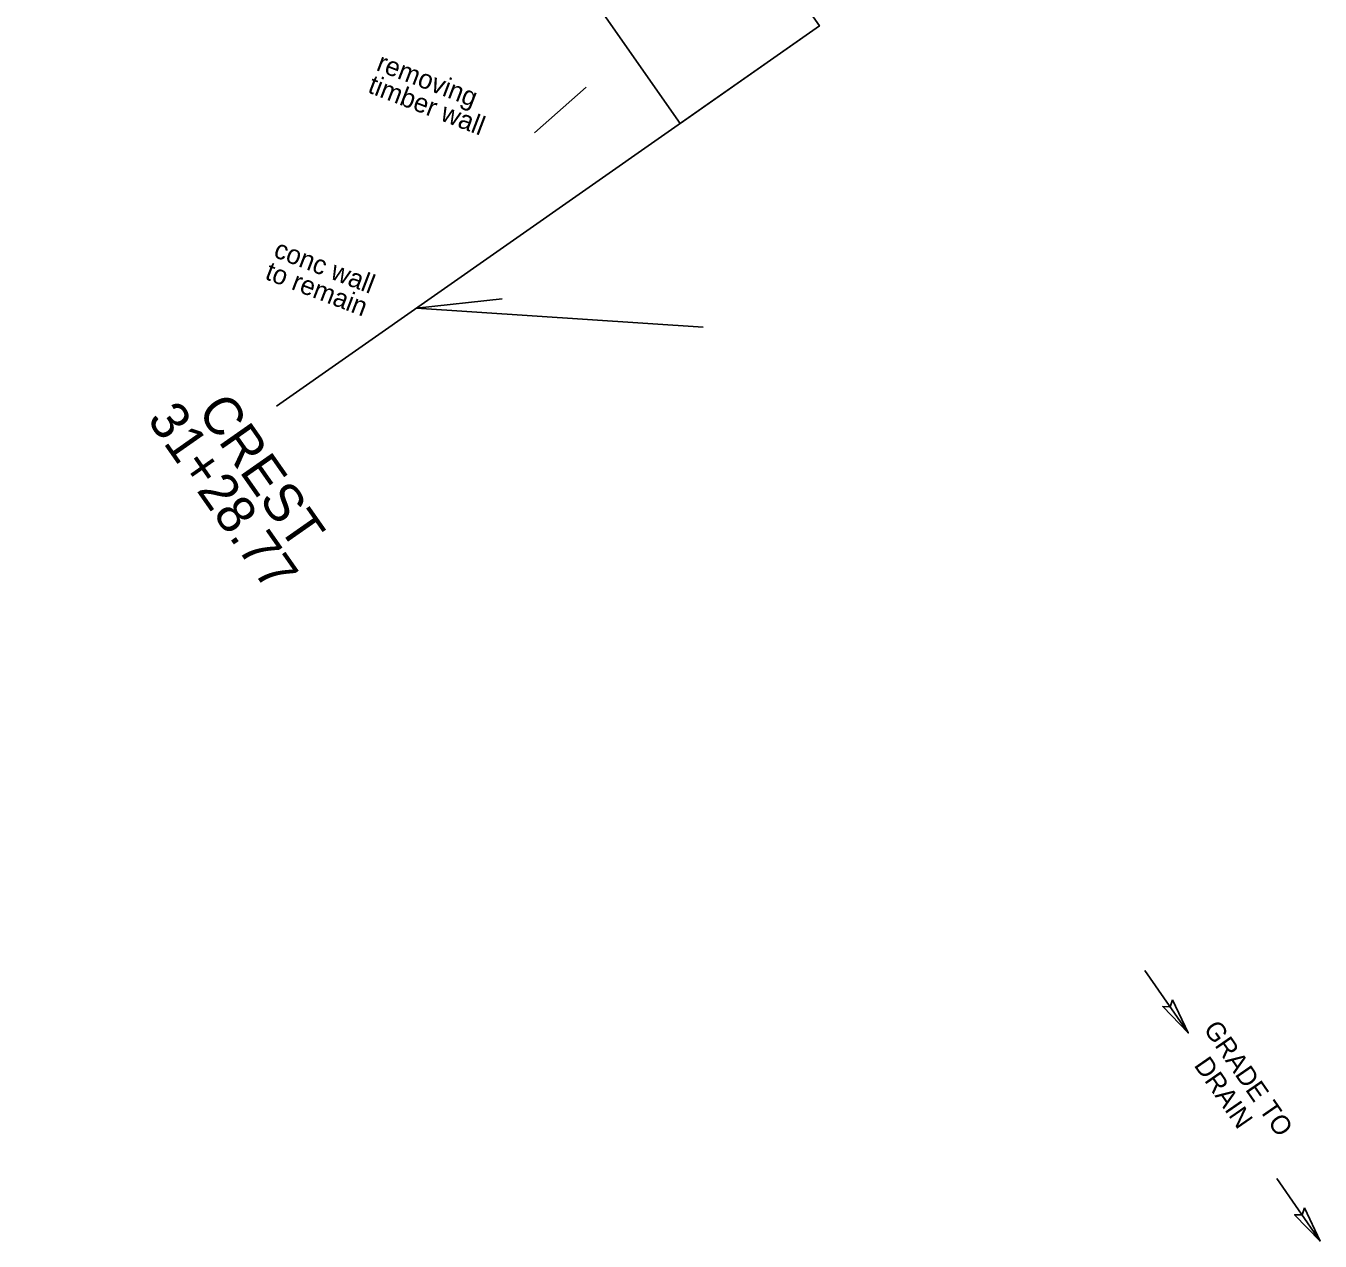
# Model space of a CAD drawing. Extents: x 2296558 to 2299313, y 599200 to 601383.
# Drawn here: x 2297941.9 to 2298145.9, y 600048.6 to 600240.1 of the extents above; entities that cross this region are included whole.
import ezdxf

# ---------------------------------------------------------------- set-up
doc = ezdxf.new("R2010")
doc.units = 0
for name, color, linetype in [('Prop Plan Preparation Crest', 7, 'Continuous'), ('Prop Plan Preparation Crest Label', 7, 'Continuous'), ('Prop Plan Preparation Grade to Drain Arrows CELL', 7, 'Continuous'), ('Prop Plan Preparation Grade to Drain Arrows Label', 7, 'Continuous'), ('Prop Plan Preparation Watershed Post Construction', 7, 'Continuous'), ('Scratch_Level_1', 7, 'Continuous')]:
    doc.layers.add(name, color=color, linetype=linetype)

msp = doc.modelspace()

# ---------------------------------------------------------------- linework, layer by layer
at = {"layer": 'Prop Plan Preparation Crest'}
msp.add_line((2297981.35, 600180.17), (2298066.92, 600240.1), dxfattribs=at)
at = {"layer": 'Prop Plan Preparation Grade to Drain Arrows CELL'}
for p, q in [((2298118.24, 600091.27), (2298125.06, 600081.4)), ((2298139.03, 600058.48), (2298145.85, 600048.6))]:
    msp.add_line(p, q, dxfattribs=at)
for points in [[(2298122.6, 600086.64), (2298125.06, 600081.4), (2298121.04, 600085.56), (2298122.22, 600085.51)], [(2298143.39, 600053.84), (2298145.85, 600048.6), (2298141.83, 600052.76), (2298143.01, 600052.72)]]:
    msp.add_lwpolyline(points, close=True, dxfattribs=at)
at = {"layer": 'Prop Plan Preparation Watershed Post Construction'}
msp.add_lwpolyline([(2297958.64, 600394.72), (2298066.92, 600240.1), (2298044.98, 600224.73), (2297959.37, 600346.97), (2297941.85, 600382.96)], dxfattribs=at)
at = {"layer": 'Scratch_Level_1'}
for p, q in [((2298022.02, 600223.22), (2298030.15, 600230.43)), ((2298003.41, 600195.62), (2298016.92, 600197.08)), ((2298003.41, 600195.62), (2298048.61, 600192.6))]:
    msp.add_line(p, q, dxfattribs=at)

# ---------------------------------------------------------------- texts
at = {"layer": 'Prop Plan Preparation Crest Label'}
for s, p in [('CREST', (2297968.76, 600179.39)), ('31+28.77', (2297960.85, 600178.06))]:
    msp.add_text(s, height=6, rotation=305.0027, dxfattribs=at).set_placement(p)
at = {"layer": 'Prop Plan Preparation Grade to Drain Arrows Label'}
for s, p in [('GRADE TO', (2298127.38, 600082.03)), (' DRAIN', (2298125.24, 600077.23))]:
    msp.add_text(s, height=3, rotation=304.6459, dxfattribs=at).set_placement(p)
at = {"layer": 'Scratch_Level_1'}
for s, p in [('removing ', (2297996.92, 600233.16)), ('timber wall', (2297995.58, 600229.66)), ('conc wall ', (2297980.72, 600203.76)), ('to remain', (2297979.37, 600200.26))]:
    msp.add_text(s, height=3, rotation=338.989, dxfattribs=at).set_placement(p)

doc.saveas('drawing.dxf')
